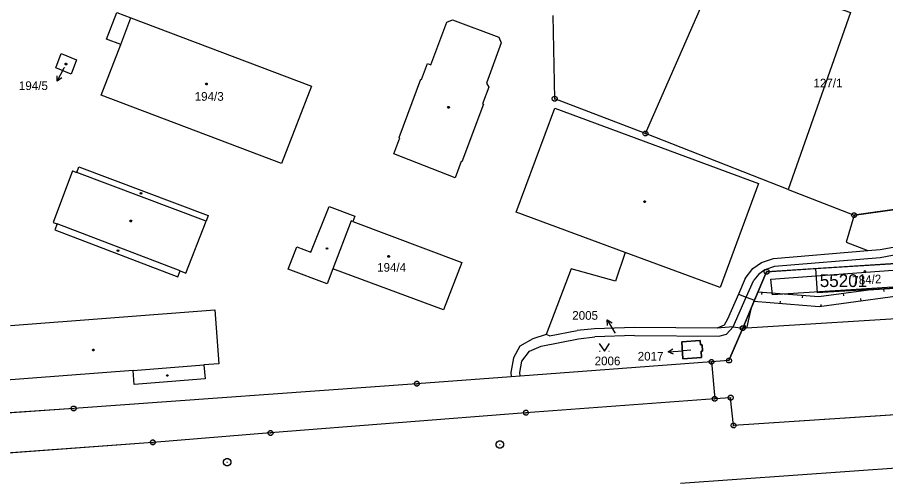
# Model space of a CAD drawing. Extents: x -777309 to -774195, y -1144706 to -1143600.
# Drawn here: x -774968.8 to -774798.5, y -1144451 to -1144360.8 of the extents above; entities that cross this region are included whole.
import ezdxf

# ---------------------------------------------------------------- set-up
doc = ezdxf.new("R2010")
doc.units = 0
for name, color, linetype in [('1', 7, 'Continuous'), ('11', 7, 'Continuous'), ('12', 7, 'Continuous'), ('13', 7, 'Continuous'), ('2', 7, 'Continuous'), ('3', 7, 'Continuous'), ('4', 7, 'Continuous'), ('5', 7, 'Continuous'), ('7', 7, 'Continuous'), ('8', 7, 'Continuous')]:
    doc.layers.add(name, color=color, linetype=linetype)

msp = doc.modelspace()

# ---------------------------------------------------------------- linework, layer by layer
at = {"layer": '1'}
for p, q in [((-774845.62, -1144383.56), (-774831.16, -1144350.65)), ((-774863.41, -1144376.75), (-774863.72, -1144360.44)), ((-774948.54, -1144366.12), (-774946.53, -1144360.9)), ((-774946.53, -1144360.9), (-774911.14, -1144374.27)), ((-774952.35, -1144376.06), (-774948.54, -1144366.12)), ((-774961.27, -1144370.7), (-774960.21, -1144367.86)), ((-774960.21, -1144367.86), (-774957.19, -1144369.08)), ((-774957.19, -1144369.08), (-774958.23, -1144371.92)), ((-774958.23, -1144371.92), (-774961.27, -1144370.7)), ((-774911.14, -1144374.27), (-774916.98, -1144389.4)), ((-774916.98, -1144389.4), (-774952.35, -1144376.06)), ((-774845.62, -1144383.56), (-774863.41, -1144376.75)), ((-774817.65, -1144394.5), (-774845.62, -1144383.56)), ((-774817.65, -1144394.5), (-774804.69, -1144399.57)), ((-774911.26, -1144406.79), (-774907.66, -1144397.86)), ((-774907.66, -1144397.86), (-774902.6, -1144399.78)), ((-774804.69, -1144399.57), (-774806.23, -1144404.86)), ((-774793.9, -1144398.06), (-774804.69, -1144399.57)), ((-774902.6, -1144399.78), (-774903, -1144400.82)), ((-774903, -1144400.82), (-774881.66, -1144408.82)), ((-774915.67, -1144410.12), (-774914.01, -1144405.75)), ((-774914.01, -1144405.75), (-774911.26, -1144406.79)), ((-774806.23, -1144404.86), (-774801.98, -1144406.47)), ((-774801.98, -1144406.47), (-774799.57, -1144406.26)), ((-774799.57, -1144406.26), (-774796.3, -1144405.69)), ((-774822.89, -1144408.84), (-774820.5, -1144408.04)), ((-774820.5, -1144408.04), (-774801.98, -1144406.47)), ((-774799.56, -1144407.9), (-774820.31, -1144409.63)), ((-774795.8, -1144407.18), (-774799.56, -1144407.9)), ((-774881.66, -1144408.82), (-774885.25, -1144418.1)), ((-774824.53, -1144410), (-774822.89, -1144408.84)), ((-774820.31, -1144409.63), (-774822.18, -1144410.3)), ((-774908.07, -1144413.02), (-774915.67, -1144410.12)), ((-774906.94, -1144410.06), (-774908.07, -1144413.02)), ((-774885.25, -1144418.1), (-774906.94, -1144410.06)), ((-774826.04, -1144411.98), (-774824.53, -1144410)), ((-774823.4, -1144411.16), (-774824.38, -1144412.31)), ((-774824.22, -1144416.24), (-774821.85, -1144410.67)), ((-774822.18, -1144410.3), (-774823.4, -1144411.16)), ((-774821.85, -1144410.67), (-774812.25, -1144410.04)), ((-774812.25, -1144410.04), (-774811.97, -1144414.8)), ((-774826.04, -1144411.98), (-774827.39, -1144415.07)), ((-774825.86, -1144415.63), (-774824.38, -1144412.31)), ((-774788.39, -1144413.36), (-774811.97, -1144414.8)), ((-774827.39, -1144415.07), (-774825.86, -1144415.63)), ((-774826.54, -1144421.73), (-774824.22, -1144416.24)), ((-774825.86, -1144415.63), (-774824.22, -1144416.24)), ((-774847.74, -1144421.57), (-774855.6, -1144421.82)), ((-774831.56, -1144421.69), (-774847.74, -1144421.57)), ((-774828.44, -1144421.43), (-774831.56, -1144421.69)), ((-774829.7, -1144422.88), (-774828.44, -1144421.43)), ((-774829.24, -1144428.08), (-774826.54, -1144421.73)), ((-774828.44, -1144421.43), (-774826.54, -1144421.73)), ((-774865.1, -1144422.99), (-774867.69, -1144423.82)), ((-774864.41, -1144423.23), (-774865.1, -1144422.99)), ((-774864.41, -1144423.23), (-774859, -1144422.2)), ((-774855.6, -1144421.82), (-774859, -1144422.2)), ((-774858.72, -1144423.78), (-774855.55, -1144423.4)), ((-774847.74, -1144423.16), (-774855.55, -1144423.4)), ((-774847.74, -1144423.16), (-774831.25, -1144423.26)), ((-774831.25, -1144423.26), (-774829.7, -1144422.88)), ((-774867.69, -1144423.82), (-774870.28, -1144425.27)), ((-774866.07, -1144425.23), (-774858.72, -1144423.78)), ((-774834.87, -1144424.15), (-774838.49, -1144424.4)), ((-774838.49, -1144424.4), (-774838.26, -1144427.74)), ((-774834.81, -1144424.99), (-774834.87, -1144424.15)), ((-774834.5, -1144424.97), (-774834.81, -1144424.99)), ((-774834.41, -1144426.21), (-774834.5, -1144424.97)), ((-774870.28, -1144425.27), (-774871.48, -1144427.55)), ((-774869.86, -1144428.16), (-774868.34, -1144426.23)), ((-774868.34, -1144426.23), (-774866.07, -1144425.23)), ((-774834.72, -1144426.24), (-774834.41, -1144426.21)), ((-774834.63, -1144427.47), (-774834.72, -1144426.24)), ((-774871.48, -1144427.55), (-774872.02, -1144430.41)), ((-774870.26, -1144430.4), (-774869.86, -1144428.16)), ((-774832.66, -1144428.33), (-774870.21, -1144431.11)), ((-774838.26, -1144427.74), (-774834.63, -1144427.47)), ((-774829.24, -1144428.08), (-774832.66, -1144428.33)), ((-774832.66, -1144428.33), (-774832.04, -1144435.58)), ((-774871.96, -1144431.24), (-774890.46, -1144432.61)), ((-774872.02, -1144430.41), (-774871.96, -1144431.24)), ((-774870.21, -1144431.11), (-774871.96, -1144431.24)), ((-774870.21, -1144431.11), (-774870.26, -1144430.4)), ((-774890.46, -1144432.61), (-774957.77, -1144437.47)), ((-774828.91, -1144435.35), (-774832.04, -1144435.58)), ((-774828.33, -1144440.79), (-774828.91, -1144435.35)), ((-774832.04, -1144435.58), (-774869.06, -1144438.3)), ((-774760.86, -1144436.38), (-774828.33, -1144440.79)), ((-774957.77, -1144437.47), (-775003.31, -1144440.57)), ((-774869.06, -1144438.3), (-774919.16, -1144442.27)), ((-774919.16, -1144442.27), (-774942.23, -1144444.12)), ((-774942.23, -1144444.12), (-775006.07, -1144448.84)), ((-774838.77, -1144452.13), (-774793.68, -1144448.91))]:
    msp.add_line(p, q, dxfattribs=at)
for points in [[(-774749.65, -1144405.72), (-774750.72, -1144408.24), (-774751.62, -1144410.36), (-774752.94, -1144413.48), (-774754.55, -1144417.27), (-774825.82, -1144421.69), (-774826.54, -1144421.73)], [(-774812.25, -1144410.04), (-774795.44, -1144408.94), (-774788.71, -1144408.47)]]:
    msp.add_lwpolyline(points, dxfattribs=at)
at = {"layer": '11'}
for points in [[(-774793.9, -1144398.06), (-774782, -1144352.41), (-774780.31, -1144345.89), (-774798.77, -1144341.16), (-774820.92, -1144335.47), (-774824.66, -1144334.51), (-774827.09, -1144338.8), (-774831.16, -1144350.65), (-774805.38, -1144359.83), (-774817.65, -1144394.5), (-774804.69, -1144399.57)], [(-774795.3, -1144410.21), (-774795.05, -1144413.55), (-774820.71, -1144415.2), (-774821.03, -1144412.09)], [(-774834.87, -1144424.15), (-774834.81, -1144424.99), (-774834.5, -1144424.97), (-774834.41, -1144426.21), (-774834.72, -1144426.24), (-774834.63, -1144427.47), (-774838.26, -1144427.74), (-774838.49, -1144424.4)]]:
    msp.add_lwpolyline(points, close=True, dxfattribs=at)
for points in [[(-774795.44, -1144408.94), (-774821.85, -1144410.67), (-774824.22, -1144416.24), (-774826.54, -1144421.73), (-774829.24, -1144428.08), (-774832.66, -1144428.33), (-774870.21, -1144431.11), (-774871.96, -1144431.24), (-774890.46, -1144432.61), (-774957.77, -1144437.47), (-775003.31, -1144440.57), (-775006.9, -1144440.82), (-775032.95, -1144440.83), (-775037.63, -1144440.85), (-775036.16, -1144437.94), (-775069.78, -1144440.38), (-775071.04, -1144440.88), (-775088.39, -1144447.82), (-775138.01, -1144449.91)], [(-774760.86, -1144436.38), (-774828.33, -1144440.79), (-774828.91, -1144435.35), (-774832.04, -1144435.58), (-774869.06, -1144438.3), (-774919.16, -1144442.27), (-774942.23, -1144444.12), (-775006.07, -1144448.84), (-775047.73, -1144454.47)]]:
    msp.add_lwpolyline(points, dxfattribs=at)
at = {"layer": '12'}
for p, q in [((-774948.54, -1144366.12), (-774946.53, -1144360.9)), ((-774946.53, -1144360.9), (-774911.14, -1144374.27)), ((-774952.35, -1144376.06), (-774948.54, -1144366.12)), ((-774961.27, -1144370.7), (-774960.21, -1144367.86)), ((-774960.21, -1144367.86), (-774957.19, -1144369.08)), ((-774957.19, -1144369.08), (-774958.23, -1144371.92)), ((-774958.23, -1144371.92), (-774961.27, -1144370.7)), ((-774911.14, -1144374.27), (-774916.98, -1144389.4)), ((-774916.98, -1144389.4), (-774952.35, -1144376.06)), ((-774903.37, -1144400.67), (-774906.94, -1144410.06)), ((-774903, -1144400.82), (-774903.37, -1144400.67)), ((-774903, -1144400.82), (-774881.66, -1144408.82)), ((-774881.66, -1144408.82), (-774885.25, -1144418.1)), ((-774885.25, -1144418.1), (-774906.94, -1144410.06)), ((-774812.25, -1144410.04), (-774811.97, -1144414.8)), ((-774788.39, -1144413.36), (-774811.97, -1144414.8))]:
    msp.add_line(p, q, dxfattribs=at)
msp.add_lwpolyline([(-774812.25, -1144410.04), (-774795.44, -1144408.94), (-774788.71, -1144408.47)], dxfattribs=at)
at = {"layer": '13'}
for p, q in [((-774822.79, -1144414.63), (-774822.83, -1144415.13)), ((-774806.87, -1144414.86), (-774806.8, -1144415.36)), ((-774798.92, -1144414), (-774798.89, -1144414.5)), ((-774819.2, -1144416.92), (-774819.16, -1144416.42)), ((-774814.82, -1144415.26), (-774814.86, -1144415.76)), ((-774803.29, -1144416.4), (-774803.36, -1144415.9)), ((-774811.22, -1144417.55), (-774811.18, -1144417.05)), ((-774825.98, -1144421.7), (-774826.01, -1144421.2))]:
    msp.add_line(p, q, dxfattribs=at)
for points in [[(-774749.65, -1144405.72), (-774750.72, -1144408.24), (-774753.96, -1144408.4), (-774779.6, -1144412.19), (-774785.85, -1144413.86), (-774790.46, -1144414.66), (-774811.56, -1144417.52), (-774824.34, -1144416.52), (-774823.51, -1144414.57), (-774811.62, -1144415.51), (-774801.84, -1144414.18), (-774788.39, -1144413.36), (-774788.46, -1144412.28), (-774786.28, -1144411.9), (-774780, -1144410.23), (-774754.16, -1144406.4), (-774751.36, -1144405.84)], [(-774826.54, -1144421.73), (-774824.96, -1144418), (-774825.82, -1144421.69)]]:
    msp.add_lwpolyline(points, close=True, dxfattribs=at)
at = {"layer": '3'}
for p, q in [((-774854.62, -1144426.23), (-774854.52, -1144426.23)), ((-774852.82, -1144426.23), (-774852.72, -1144426.23))]:
    msp.add_line(p, q, dxfattribs=at)
msp.add_lwpolyline([(-774854.67, -1144424.73), (-774853.67, -1144426.23), (-774852.67, -1144424.73)], dxfattribs=at)
at = {"layer": '4'}
for p, q in [((-774951.35, -1144365.04), (-774949.33, -1144359.83)), ((-774949.33, -1144359.83), (-774946.53, -1144360.9)), ((-774887.73, -1144370.07), (-774884.58, -1144361.71)), ((-774884.58, -1144361.71), (-774883.44, -1144361.25)), ((-774883.44, -1144361.25), (-774874.4, -1144364.63)), ((-774948.54, -1144366.12), (-774951.35, -1144365.04)), ((-774874.4, -1144364.63), (-774873.91, -1144365.74)), ((-774873.91, -1144365.74), (-774876.81, -1144373.7)), ((-774889.53, -1144372.93), (-774888.38, -1144369.85)), ((-774888.38, -1144369.85), (-774887.73, -1144370.07)), ((-774893.94, -1144384.31), (-774889.67, -1144372.88)), ((-774889.67, -1144372.88), (-774889.53, -1144372.93)), ((-774876.81, -1144373.7), (-774876.33, -1144374.46)), ((-774876.33, -1144374.46), (-774877.55, -1144377.73)), ((-774877.41, -1144377.78), (-774881.61, -1144389.11)), ((-774877.55, -1144377.73), (-774877.41, -1144377.78)), ((-774870.95, -1144398.98), (-774863.38, -1144378.61)), ((-774863.38, -1144378.61), (-774823.46, -1144393.35)), ((-774893.8, -1144384.37), (-774893.94, -1144384.31)), ((-774894.99, -1144387.55), (-774893.8, -1144384.37)), ((-774882.93, -1144392.23), (-774894.99, -1144387.55)), ((-774881.75, -1144389.05), (-774882.93, -1144392.23)), ((-774881.61, -1144389.11), (-774881.75, -1144389.05)), ((-774957.99, -1144390.88), (-774961.79, -1144400.99)), ((-774957.99, -1144390.88), (-774957.18, -1144391.19)), ((-774957.18, -1144391.19), (-774956.76, -1144390.06)), ((-774956.76, -1144390.06), (-774931.38, -1144399.6)), ((-774931.8, -1144400.73), (-774957.18, -1144391.19)), ((-774823.46, -1144393.35), (-774830.99, -1144413.74)), ((-774931.38, -1144399.6), (-774931.8, -1144400.73)), ((-774849.61, -1144406.86), (-774870.95, -1144398.98)), ((-774961.79, -1144400.99), (-774961, -1144401.29)), ((-774961, -1144401.29), (-774961.44, -1144402.45)), ((-774936.89, -1144410.46), (-774961, -1144401.29)), ((-774935.74, -1144410.9), (-774931.8, -1144400.73)), ((-774903.37, -1144400.67), (-774906.94, -1144410.06)), ((-774903, -1144400.82), (-774903.37, -1144400.67)), ((-774961.44, -1144402.45), (-774937.34, -1144411.63)), ((-774849.61, -1144406.86), (-774851.49, -1144412.52)), ((-774830.99, -1144413.74), (-774849.61, -1144406.86)), ((-774937.34, -1144411.63), (-774936.89, -1144410.46)), ((-774936.89, -1144410.46), (-774935.74, -1144410.9)), ((-774860.16, -1144410.07), (-774865.1, -1144422.99)), ((-774851.49, -1144412.52), (-774860.16, -1144410.07)), ((-774827.39, -1144415.07), (-774829.53, -1144419.94)), ((-774828.44, -1144421.43), (-774825.86, -1144415.63)), ((-774970.13, -1144421.2), (-774930.07, -1144418.15)), ((-774930.07, -1144418.15), (-774929.27, -1144428.7)), ((-774829.53, -1144419.94), (-774830.18, -1144421.12)), ((-774830.18, -1144421.12), (-774831.56, -1144421.69)), ((-774946.09, -1144429.99), (-774978.21, -1144432.45)), ((-774946.09, -1144429.99), (-774932.21, -1144428.93)), ((-774945.88, -1144432.74), (-774946.09, -1144429.99)), ((-774929.27, -1144428.7), (-774932.21, -1144428.93)), ((-774932.21, -1144428.93), (-774932, -1144431.68)), ((-774932, -1144431.68), (-774945.88, -1144432.74))]:
    msp.add_line(p, q, dxfattribs=at)
at = {"layer": '5'}
for points in [[(-774959.27, -1144369.75), (-774959.17, -1144369.77), (-774959.12, -1144369.86), (-774959.1, -1144369.92), (-774959.12, -1144370.01), (-774959.2, -1144370.08), (-774959.27, -1144370.09), (-774959.36, -1144370.06), (-774959.42, -1144370), (-774959.44, -1144369.92), (-774959.42, -1144369.83), (-774959.34, -1144369.76)], [(-774931.73, -1144373.66), (-774931.63, -1144373.68), (-774931.58, -1144373.77), (-774931.56, -1144373.83), (-774931.58, -1144373.92), (-774931.66, -1144373.99), (-774931.73, -1144374), (-774931.82, -1144373.97), (-774931.88, -1144373.91), (-774931.9, -1144373.83), (-774931.88, -1144373.74), (-774931.8, -1144373.67)], [(-774884.15, -1144378.28), (-774884.06, -1144378.43), (-774884.15, -1144378.58), (-774884.33, -1144378.58), (-774884.42, -1144378.43), (-774884.33, -1144378.28)], [(-774944.46, -1144395.13), (-774944.37, -1144395.28), (-774944.46, -1144395.43), (-774944.64, -1144395.43), (-774944.73, -1144395.28), (-774944.64, -1144395.13)], [(-774845.7, -1144396.78), (-774845.61, -1144396.93), (-774845.7, -1144397.08), (-774845.88, -1144397.08), (-774845.97, -1144396.93), (-774845.88, -1144396.78)], [(-774946.48, -1144400.56), (-774946.39, -1144400.71), (-774946.48, -1144400.86), (-774946.66, -1144400.86), (-774946.75, -1144400.71), (-774946.66, -1144400.56)], [(-774948.97, -1144406.39), (-774948.88, -1144406.54), (-774948.97, -1144406.69), (-774949.15, -1144406.69), (-774949.24, -1144406.54), (-774949.15, -1144406.39)], [(-774907.99, -1144405.95), (-774907.9, -1144406.1), (-774907.99, -1144406.25), (-774908.17, -1144406.25), (-774908.26, -1144406.1), (-774908.17, -1144405.95)], [(-774895.97, -1144407.47), (-774895.87, -1144407.49), (-774895.82, -1144407.58), (-774895.8, -1144407.64), (-774895.82, -1144407.73), (-774895.9, -1144407.8), (-774895.97, -1144407.81), (-774896.06, -1144407.78), (-774896.12, -1144407.72), (-774896.14, -1144407.64), (-774896.12, -1144407.55), (-774896.04, -1144407.48)], [(-774802.6, -1144410.44), (-774802.5, -1144410.46), (-774802.45, -1144410.55), (-774802.43, -1144410.61), (-774802.45, -1144410.7), (-774802.53, -1144410.77), (-774802.6, -1144410.78), (-774802.69, -1144410.75), (-774802.75, -1144410.69), (-774802.77, -1144410.61), (-774802.75, -1144410.52), (-774802.67, -1144410.45)], [(-774953.84, -1144425.84), (-774953.75, -1144425.99), (-774953.84, -1144426.14), (-774954.02, -1144426.14), (-774954.11, -1144425.99), (-774954.02, -1144425.84)], [(-774939.3, -1144430.85), (-774939.21, -1144431), (-774939.3, -1144431.15), (-774939.48, -1144431.15), (-774939.57, -1144431), (-774939.48, -1144430.85)]]:
    msp.add_lwpolyline(points, close=True, dxfattribs=at)
at = {"layer": '7'}
for p, q in [((-774961.02, -1144373.32), (-774959.66, -1144370.65)), ((-774959.63, -1144370.59), (-774959.66, -1144370.65)), ((-774853.11, -1144420.07), (-774851.6, -1144422.66)), ((-774851.6, -1144422.67), (-774851.6, -1144422.66)), ((-774841.19, -1144426.37), (-774838.2, -1144426.14)), ((-774836.71, -1144426.02), (-774838.2, -1144426.14))]:
    msp.add_line(p, q, dxfattribs=at)
for points in [[(-774960.12, -1144372.66), (-774961.02, -1144373.32), (-774961.01, -1144372.21)], [(-774853.04, -1144421.18), (-774853.11, -1144420.07), (-774852.17, -1144420.68)], [(-774840.15, -1144426.79), (-774841.19, -1144426.37), (-774840.23, -1144425.8)]]:
    msp.add_lwpolyline(points, dxfattribs=at)
at = {"layer": '8'}
for p, q in [((-774863.53, -1144376.75), (-774863.29, -1144376.75)), ((-774845.74, -1144383.56), (-774845.5, -1144383.56)), ((-774804.81, -1144399.57), (-774804.57, -1144399.57)), ((-774821.97, -1144410.67), (-774821.73, -1144410.67)), ((-774826.66, -1144421.73), (-774826.42, -1144421.73)), ((-774832.78, -1144428.33), (-774832.54, -1144428.33)), ((-774829.36, -1144428.08), (-774829.12, -1144428.08)), ((-774890.58, -1144432.61), (-774890.34, -1144432.61)), ((-774829.03, -1144435.35), (-774828.79, -1144435.35)), ((-774832.16, -1144435.58), (-774831.92, -1144435.58)), ((-774957.89, -1144437.47), (-774957.65, -1144437.47)), ((-774869.18, -1144438.3), (-774868.94, -1144438.3)), ((-774828.45, -1144440.79), (-774828.21, -1144440.79)), ((-774919.28, -1144442.27), (-774919.04, -1144442.27)), ((-774942.35, -1144444.12), (-774942.11, -1144444.12)), ((-774874.23, -1144444.54), (-774874.13, -1144444.54)), ((-774927.72, -1144447.97), (-774927.62, -1144447.97))]:
    msp.add_line(p, q, dxfattribs=at)
for points in [[(-774863.26, -1144376.27), (-774863.01, -1144376.45), (-774862.91, -1144376.74), (-774863.01, -1144377.03), (-774863.26, -1144377.21), (-774863.57, -1144377.21), (-774863.82, -1144377.03), (-774863.92, -1144376.74), (-774863.82, -1144376.45), (-774863.57, -1144376.27)], [(-774845.47, -1144383.08), (-774845.22, -1144383.26), (-774845.12, -1144383.55), (-774845.22, -1144383.84), (-774845.47, -1144384.02), (-774845.78, -1144384.02), (-774846.03, -1144383.84), (-774846.13, -1144383.55), (-774846.03, -1144383.26), (-774845.78, -1144383.08)], [(-774804.54, -1144399.09), (-774804.29, -1144399.27), (-774804.19, -1144399.56), (-774804.29, -1144399.85), (-774804.54, -1144400.03), (-774804.85, -1144400.03), (-774805.1, -1144399.85), (-774805.2, -1144399.56), (-774805.1, -1144399.27), (-774804.85, -1144399.09)], [(-774821.7, -1144410.19), (-774821.45, -1144410.37), (-774821.35, -1144410.66), (-774821.45, -1144410.95), (-774821.7, -1144411.13), (-774822.01, -1144411.13), (-774822.26, -1144410.95), (-774822.36, -1144410.66), (-774822.26, -1144410.37), (-774822.01, -1144410.19)], [(-774826.39, -1144421.25), (-774826.14, -1144421.43), (-774826.04, -1144421.72), (-774826.14, -1144422.01), (-774826.39, -1144422.19), (-774826.7, -1144422.19), (-774826.95, -1144422.01), (-774827.05, -1144421.72), (-774826.95, -1144421.43), (-774826.7, -1144421.25)], [(-774832.51, -1144427.85), (-774832.26, -1144428.03), (-774832.16, -1144428.32), (-774832.26, -1144428.61), (-774832.51, -1144428.79), (-774832.82, -1144428.79), (-774833.07, -1144428.61), (-774833.17, -1144428.32), (-774833.07, -1144428.03), (-774832.82, -1144427.85)], [(-774829.09, -1144427.6), (-774828.84, -1144427.78), (-774828.74, -1144428.07), (-774828.84, -1144428.36), (-774829.09, -1144428.54), (-774829.4, -1144428.54), (-774829.65, -1144428.36), (-774829.75, -1144428.07), (-774829.65, -1144427.78), (-774829.4, -1144427.6)], [(-774890.31, -1144432.13), (-774890.06, -1144432.31), (-774889.96, -1144432.6), (-774890.06, -1144432.89), (-774890.31, -1144433.07), (-774890.62, -1144433.07), (-774890.87, -1144432.89), (-774890.97, -1144432.6), (-774890.87, -1144432.31), (-774890.62, -1144432.13)], [(-774831.89, -1144435.1), (-774831.64, -1144435.28), (-774831.54, -1144435.57), (-774831.64, -1144435.86), (-774831.89, -1144436.04), (-774832.2, -1144436.04), (-774832.45, -1144435.86), (-774832.55, -1144435.57), (-774832.45, -1144435.28), (-774832.2, -1144435.1)], [(-774828.76, -1144434.87), (-774828.51, -1144435.05), (-774828.41, -1144435.34), (-774828.51, -1144435.63), (-774828.76, -1144435.81), (-774829.07, -1144435.81), (-774829.32, -1144435.63), (-774829.42, -1144435.34), (-774829.32, -1144435.05), (-774829.07, -1144434.87)], [(-774957.62, -1144436.99), (-774957.37, -1144437.17), (-774957.27, -1144437.46), (-774957.37, -1144437.75), (-774957.62, -1144437.93), (-774957.93, -1144437.93), (-774958.18, -1144437.75), (-774958.28, -1144437.46), (-774958.18, -1144437.17), (-774957.93, -1144436.99)], [(-774868.91, -1144437.82), (-774868.66, -1144438), (-774868.56, -1144438.29), (-774868.66, -1144438.58), (-774868.91, -1144438.76), (-774869.22, -1144438.76), (-774869.47, -1144438.58), (-774869.57, -1144438.29), (-774869.47, -1144438), (-774869.22, -1144437.82)], [(-774828.18, -1144440.31), (-774827.93, -1144440.49), (-774827.83, -1144440.78), (-774827.93, -1144441.07), (-774828.18, -1144441.25), (-774828.49, -1144441.25), (-774828.74, -1144441.07), (-774828.84, -1144440.78), (-774828.74, -1144440.49), (-774828.49, -1144440.31)], [(-774919.01, -1144441.79), (-774918.76, -1144441.97), (-774918.66, -1144442.26), (-774918.76, -1144442.55), (-774919.01, -1144442.73), (-774919.32, -1144442.73), (-774919.57, -1144442.55), (-774919.67, -1144442.26), (-774919.57, -1144441.97), (-774919.32, -1144441.79)], [(-774942.08, -1144443.64), (-774941.83, -1144443.82), (-774941.73, -1144444.11), (-774941.83, -1144444.4), (-774942.08, -1144444.58), (-774942.39, -1144444.58), (-774942.64, -1144444.4), (-774942.74, -1144444.11), (-774942.64, -1144443.82), (-774942.39, -1144443.64)], [(-774873.99, -1144443.82), (-774873.65, -1144444.01), (-774873.46, -1144444.35), (-774873.46, -1144444.74), (-774873.65, -1144445.08), (-774873.99, -1144445.27), (-774874.38, -1144445.27), (-774874.72, -1144445.08), (-774874.91, -1144444.74), (-774874.91, -1144444.35), (-774874.72, -1144444.01), (-774874.38, -1144443.82)], [(-774927.48, -1144447.25), (-774927.14, -1144447.44), (-774926.95, -1144447.78), (-774926.95, -1144448.17), (-774927.14, -1144448.51), (-774927.48, -1144448.7), (-774927.87, -1144448.7), (-774928.21, -1144448.51), (-774928.4, -1144448.17), (-774928.4, -1144447.78), (-774928.21, -1144447.44), (-774927.87, -1144447.25)]]:
    msp.add_lwpolyline(points, close=True, dxfattribs=at)

# ---------------------------------------------------------------- texts
at = {"layer": '11'}
msp.add_text('55201', height=2.5, dxfattribs=at).set_placement((-774811.43, -1144413.65))
at = {"layer": '2'}
for s, height, p in [('194/5', 0.1, (-774959.61, -1144370.59)), ('127/1', 1.7, (-774812.67, -1144374.51)), ('194/3', 1.7, (-774934.03, -1144377.13)), ('194/4', 1.7, (-774898.25, -1144410.65)), ('2005', 0.1, (-774851.59, -1144422.67)), ('2017', 0.1, (-774836.7, -1144426.02)), ('2006', 1.7, (-774855.59, -1144428.99))]:
    msp.add_text(s, height=height, dxfattribs=at).set_placement(p)
msp.add_text('784/2', height=1.7, rotation=3.7242, dxfattribs=at).set_placement((-774804.98, -1144413.25))
at = {"layer": '7'}
for s, p in [('194/5', (-774968.52, -1144375.02)), ('2005', (-774859.98, -1144420.07)), ('2017', (-774847.14, -1144428.07))]:
    msp.add_text(s, height=1.7, dxfattribs=at).set_placement(p)

doc.saveas('drawing.dxf')
